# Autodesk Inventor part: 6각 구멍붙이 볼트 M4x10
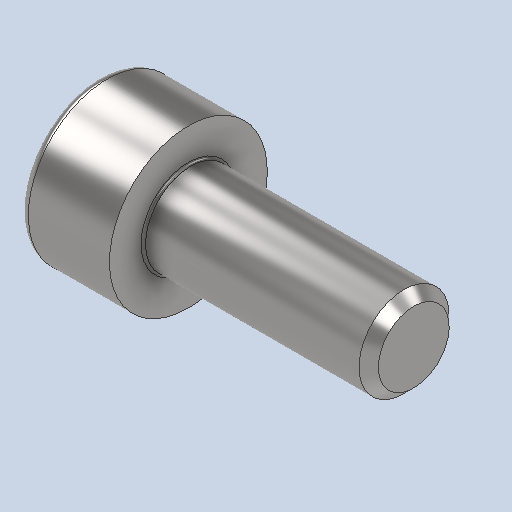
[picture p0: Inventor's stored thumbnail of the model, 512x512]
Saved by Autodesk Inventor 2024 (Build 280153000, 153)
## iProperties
Created: 2026-01
Part Number: 6각 구멍붙이 볼트 M4x10
Material: 강철, 연강
Description: 6각머리 태핑 나사
Document SubType Name: Modeling
Designer: 2-10
Density: 7.85 g/cm^3
Appearance: 기본값
Author: jhkim
Sending System: Autodesk Inventor 2026
Preprocessor: ST-DEVELOPER v20.1
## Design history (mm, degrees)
node "6각 구멍붙이 볼트 M4x101"
node "솔리드1"
body "Solid1"
